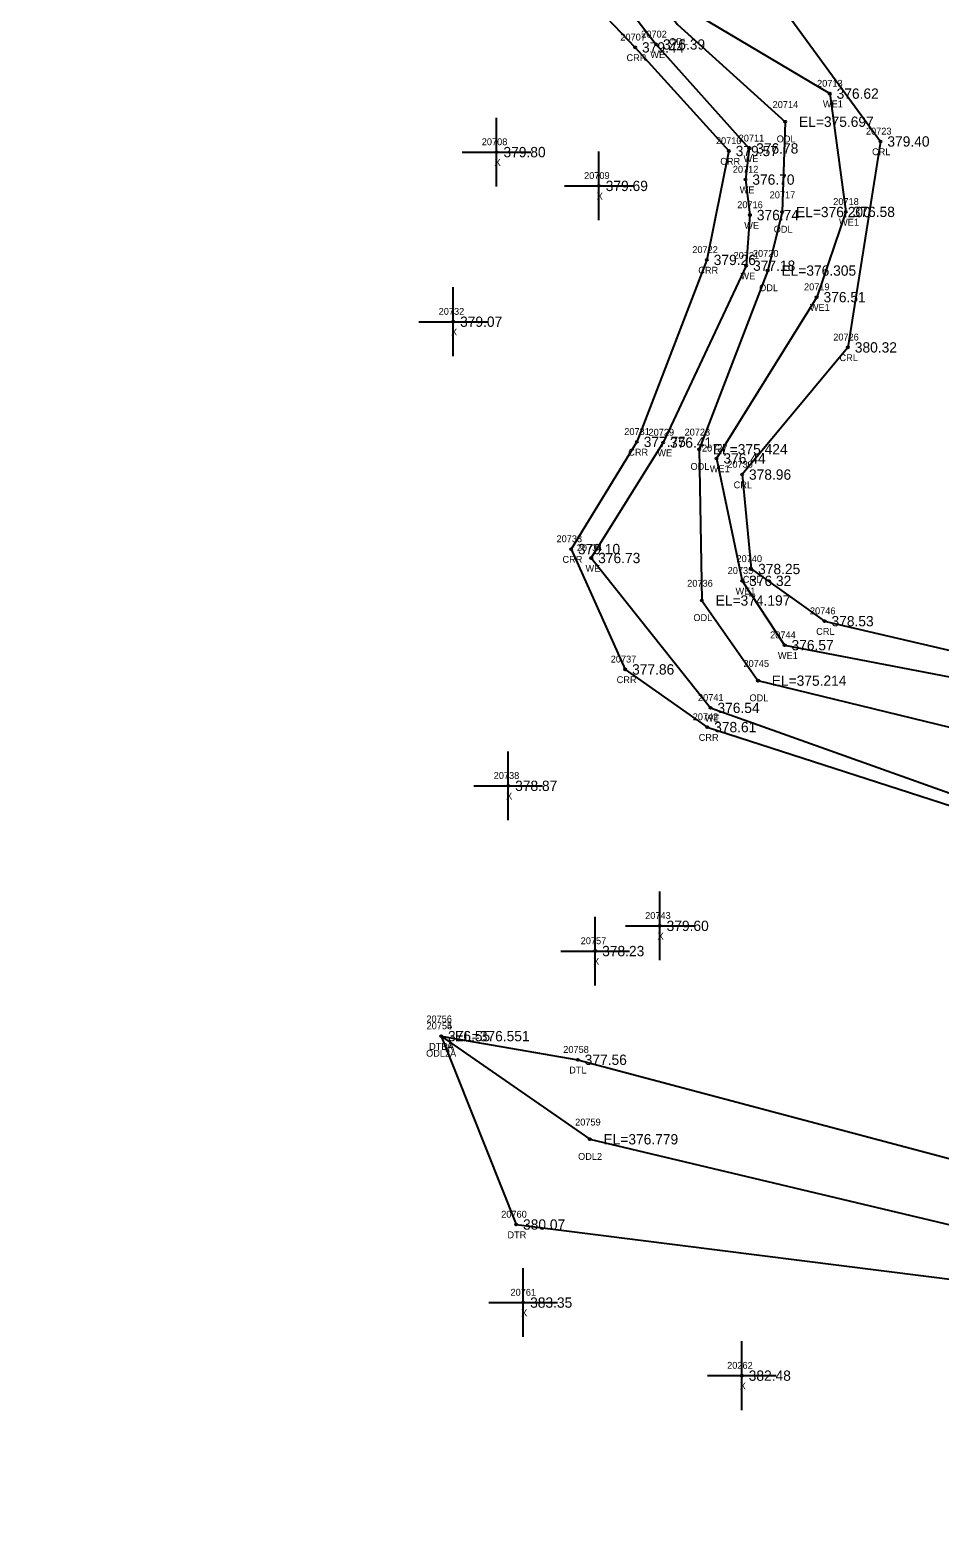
# Model space of a CAD drawing. Extents: x 2116373 to 2118139, y 979529 to 981026.
# Drawn here: x 2117048.4 to 2117180.8, y 980127.3 to 980346.7 of the extents above; entities that cross this region are included whole.
import ezdxf

# ---------------------------------------------------------------- set-up
doc = ezdxf.new("R2010")
doc.units = 0
for name, color, linetype in [('RD_EX_H2O', 7, 'Continuous'), ('RD_EX_H2O_txCode', 7, 'Continuous'), ('RD_EX_Misc', 7, 'Continuous'), ('RD_EX_Misc_txCode', 7, 'Continuous'), ('RD_EX_TX_H2O_ELEV', 7, 'Continuous'), ('RD_EX_TX_Misc_ELEV', 7, 'Continuous'), ('RD_SMD_Locator', 7, 'Continuous')]:
    doc.layers.add(name, color=color, linetype=linetype)

msp = doc.modelspace()

# ---------------------------------------------------------------- linework, layer by layer
at = {"layer": 'RD_EX_H2O'}
for points in [[(2117055.27, 980533.4), (2117084.87, 980468.5), (2117113.12, 980396.82), (2117150.26, 980360.48), (2117172.14, 980330.53), (2117167.4, 980300.56), (2117152, 980282.05), (2117153.33, 980268.31), (2117164.01, 980260.72), (2117221.6, 980247.26), (2117265.25, 980211.02), (2117324.27, 980199.15), (2117347.37, 980175.31), (2117365.85, 980182.55), (2117389.45, 980162.29), (2117399.63, 980142.01), (2117411.26, 980120.88), (2117420.42, 980068.64), (2117446.24, 980057.21), (2117497.11, 980045.39), (2117594.71, 979999.33), (2117646.33, 979985.56), (2117750.91, 980032.44), (2117805.09, 980018.87)], [(2117050.82, 980532.07), (2117080.88, 980466.55), (2117110.64, 980395.71), (2117144.25, 980349.68), (2117164.75, 980337.49), (2117167.1, 980320.28), (2117162.85, 980307.87), (2117148.28, 980284.4), (2117152.02, 980266.59), (2117158.19, 980257.22), (2117219.84, 980245.38), (2117260.42, 980200.03), (2117320.83, 980195.76), (2117348.44, 980166.4)], [(2117046.35, 980528.47), (2117072.74, 980464.26), (2117103.18, 980398.05), (2117142.6, 980347.56), (2117158.28, 980333.4), (2117157.84, 980320.26), (2117155.72, 980311.74), (2117145.74, 980285.73), (2117146.15, 980263.73), (2117154.31, 980252.06), (2117214.06, 980237.52), (2117257.08, 980196.51), (2117314.34, 980190.71), (2117327.56, 980176.76), (2117343.89, 980156.23)], [(2117042.29, 980526.09), (2117065.56, 980461.15), (2117099.14, 980397), (2117139.48, 980344.65), (2117153.05, 980329.52), (2117152.49, 980324.98), (2117153.14, 980319.82), (2117152.6, 980312.45), (2117140.5, 980286.71), (2117130.05, 980269.91), (2117147.41, 980248.1), (2117202.36, 980228.49), (2117250.8, 980193.52), (2117312.93, 980184.75), (2117333.66, 980167.27), (2117332.31, 980165.61), (2117330.39, 980165.66), (2117305.03, 980166.54), (2117306.15, 980158.45), (2117334.27, 980149.08), (2117359.88, 980134.92)], [(2117031.59, 980522.05), (2117061.22, 980460.91), (2117085.86, 980397.22), (2117136.43, 980344.22), (2117150.07, 980329.14), (2117146.87, 980313.29), (2117136.68, 980286.81), (2117127.11, 980271.21), (2117134.99, 980253.7), (2117146.93, 980245.3), (2117201.17, 980227.79), (2117241.16, 980199.52)], [(2117108.2, 980200.33), (2117129.82, 980185.32), (2117196.35, 980169.53), (2117205.12, 980176.93), (2117214.41, 980186.14), (2117250.8, 980193.52)], [(2117108.2, 980200.33), (2117119.12, 980172.91), (2117196.12, 980163.21), (2117213.19, 980174.82), (2117253.76, 980181.57)], [(2117108.2, 980200.33), (2117128.09, 980196.89), (2117197.27, 980178.49), (2117200.29, 980179.87), (2117210.97, 980190.02), (2117241.16, 980199.52)]]:
    msp.add_lwpolyline(points, dxfattribs=at)
at = {"layer": 'RD_EX_Misc'}
for p, q in [((2117116.27, 980323.98), (2117116.27, 980333.98)), ((2117111.27, 980328.98), (2117121.27, 980328.98)), ((2117131.15, 980319.06), (2117131.15, 980329.06)), ((2117126.15, 980324.06), (2117136.15, 980324.06)), ((2117109.96, 980299.3), (2117109.96, 980309.3)), ((2117104.96, 980304.3), (2117114.96, 980304.3)), ((2117117.97, 980231.76), (2117117.97, 980241.76)), ((2117112.97, 980236.76), (2117122.97, 980236.76)), ((2117140.01, 980211.38), (2117140.01, 980221.38)), ((2117130.63, 980207.71), (2117130.63, 980217.71)), ((2117135.01, 980216.38), (2117145.01, 980216.38)), ((2117125.63, 980212.71), (2117135.63, 980212.71)), ((2117120.15, 980156.55), (2117120.15, 980166.55)), ((2117115.15, 980161.55), (2117125.15, 980161.55)), ((2117151.96, 980145.92), (2117151.96, 980155.92)), ((2117146.96, 980150.92), (2117156.96, 980150.92))]:
    msp.add_line(p, q, dxfattribs=at)
at = {"layer": 'RD_SMD_Locator'}
for centre in [(2117136.43, 980344.22), (2117139.48, 980344.65), (2117164.75, 980337.49), (2117158.28, 980333.4), (2117172.14, 980330.53), (2117116.27, 980328.98), (2117150.07, 980329.14), (2117153.05, 980329.52), (2117131.15, 980324.06), (2117152.49, 980324.98), (2117153.14, 980319.82), (2117157.84, 980320.26), (2117167.1, 980320.28), (2117146.87, 980313.29), (2117152.6, 980312.45), (2117155.72, 980311.74), (2117162.85, 980307.87), (2117109.96, 980304.3), (2117167.4, 980300.56), (2117136.68, 980286.81), (2117140.5, 980286.71), (2117145.74, 980285.73), (2117148.28, 980284.4), (2117152, 980282.05), (2117127.11, 980271.21), (2117130.05, 980269.91), (2117153.33, 980268.31), (2117152.02, 980266.59), (2117146.15, 980263.73), (2117164.01, 980260.72), (2117158.19, 980257.22), (2117134.99, 980253.7), (2117154.31, 980252.06), (2117147.41, 980248.1), (2117146.93, 980245.3), (2117117.97, 980236.76), (2117140.01, 980216.38), (2117130.63, 980212.71), (2117108.2, 980200.33), (2117108.2, 980200.33), (2117108.2, 980200.33), (2117128.09, 980196.89), (2117129.82, 980185.32), (2117119.12, 980172.91), (2117120.15, 980161.55), (2117151.96, 980150.92)]:
    msp.add_circle(centre, 0.15, dxfattribs=at)

# ---------------------------------------------------------------- texts
at = {"layer": 'RD_EX_H2O_txCode'}
for s, p in [('20707', (2117134.28, 980345.22)), ('20702', (2117137.32, 980345.65)), ('WE', (2117138.64, 980342.65)), ('ODL', (2117141.36, 980344.56)), ('CRR', (2117135.18, 980342.22)), ('20713', (2117162.91, 980338.49)), ('20714', (2117156.44, 980335.4)), ('WE1', (2117163.76, 980335.49)), ('20710', (2117148.19, 980330.14)), ('20711', (2117151.5, 980330.52)), ('ODL', (2117157.03, 980330.4)), ('20723', (2117170.02, 980331.53)), ('WE', (2117152.21, 980327.52)), ('CRL', (2117170.91, 980328.53)), ('CRR', (2117148.82, 980327.14)), ('20712', (2117150.65, 980325.98)), ('WE', (2117151.65, 980322.98)), ('20716', (2117151.29, 980320.82)), ('20717', (2117156.01, 980322.26)), ('20718', (2117165.26, 980321.28)), ('WE', (2117152.31, 980317.82)), ('ODL', (2117156.6, 980317.26)), ('WE1', (2117166.11, 980318.28)), ('20722', (2117144.75, 980314.29)), ('20721', (2117150.76, 980313.45)), ('20720', (2117153.57, 980313.74)), ('CRR', (2117145.62, 980311.29)), ('WE', (2117151.76, 980310.45)), ('ODL', (2117154.48, 980308.74)), ('20719', (2117161.01, 980308.87)), ('WE1', (2117161.86, 980305.87)), ('20726', (2117165.26, 980301.56)), ('CRL', (2117166.17, 980298.56)), ('20731', (2117134.85, 980287.81)), ('20729', (2117138.38, 980287.71)), ('20728', (2117143.62, 980287.73)), ('CRR', (2117135.43, 980284.81)), ('WE', (2117139.66, 980284.71)), ('20727', (2117146.16, 980285.4)), ('ODL', (2117144.49, 980282.73)), ('WE1', (2117147.29, 980282.4)), ('20730', (2117149.84, 980283.05)), ('CRL', (2117150.77, 980280.05)), ('20733', (2117124.99, 980272.21)), ('20734', (2117127.93, 980270.91)), ('CRR', (2117125.86, 980269.21)), ('20740', (2117151.18, 980269.31)), ('WE', (2117129.21, 980267.91)), ('20735', (2117149.9, 980267.59)), ('CRL', (2117152.11, 980266.31)), ('20736', (2117144.01, 980265.73)), ('WE1', (2117151.04, 980264.59)), ('20746', (2117161.87, 980261.72)), ('ODL', (2117144.91, 980260.73)), ('20744', (2117156.08, 980258.22)), ('CRL', (2117162.78, 980258.72)), ('WE1', (2117157.21, 980255.22)), ('20737', (2117132.88, 980254.7)), ('20745', (2117152.2, 980254.06)), ('CRR', (2117133.74, 980251.7)), ('20741', (2117145.58, 980249.1)), ('ODL', (2117153.07, 980249.06)), ('20742', (2117144.81, 980246.3)), ('WE', (2117146.57, 980246.1)), ('CRR', (2117145.68, 980243.3)), ('20756', (2117106.05, 980202.33)), ('20754', (2117106.08, 980201.33)), ('20755', (2117106.08, 980201.33)), ('DTRA', (2117106.44, 980198.33)), ('DTLA', (2117106.46, 980198.33)), ('20758', (2117125.97, 980197.89)), ('ODL2A', (2117106.01, 980197.33)), ('DTL', (2117126.84, 980194.89)), ('20759', (2117127.7, 980187.32)), ('ODL2', (2117128.13, 980182.32)), ('20760', (2117116.94, 980173.91)), ('DTR', (2117117.85, 980170.91))]:
    msp.add_text(s, height=1, dxfattribs=at).set_placement(p)
at = {"layer": 'RD_EX_Misc_txCode'}
for s, p in [('20708', (2117114.11, 980329.98)), ('X', (2117115.96, 980326.98)), ('20709', (2117129, 980325.06)), ('X', (2117130.84, 980322.06)), ('20732', (2117107.84, 980305.3)), ('X', (2117109.64, 980302.3)), ('20738', (2117115.85, 980237.76)), ('X', (2117117.65, 980234.76)), ('20743', (2117137.89, 980217.38)), ('20757', (2117128.51, 980213.71)), ('X', (2117139.69, 980214.38)), ('X', (2117130.32, 980210.71)), ('20761', (2117118.29, 980162.55)), ('X', (2117119.84, 980159.55)), ('20262', (2117149.82, 980151.92)), ('X', (2117151.65, 980148.92))]:
    msp.add_text(s, height=1, dxfattribs=at).set_placement(p)
at = {"layer": 'RD_EX_TX_H2O_ELEV'}
for s, p in [('379.44', (2117137.43, 980343.47)), ('376.39', (2117140.48, 980343.9)), ('376.62', (2117165.75, 980336.74)), ('EL=375.697', (2117160.28, 980332.65)), ('379.40', (2117173.14, 980329.78)), ('379.57', (2117151.07, 980328.39)), ('376.78', (2117154.05, 980328.77)), ('376.70', (2117153.49, 980324.23)), ('376.74', (2117154.14, 980319.07)), ('EL=376.200', (2117159.84, 980319.51)), ('376.58', (2117168.1, 980319.53)), ('379.26', (2117147.87, 980312.54)), ('377.18', (2117153.6, 980311.7)), ('EL=376.305', (2117157.72, 980310.99)), ('376.51', (2117163.85, 980307.12)), ('380.32', (2117168.4, 980299.81)), ('377.75', (2117137.68, 980286.06)), ('376.41', (2117141.5, 980285.96)), ('EL=375.424', (2117147.74, 980284.98)), ('376.44', (2117149.28, 980283.65)), ('378.96', (2117153, 980281.3)), ('379.10', (2117128.11, 980270.46)), ('376.73', (2117131.05, 980269.16)), ('378.25', (2117154.33, 980267.56)), ('376.32', (2117153.02, 980265.84)), ('EL=374.197', (2117148.15, 980262.98)), ('378.53', (2117165.01, 980259.97)), ('376.57', (2117159.19, 980256.47)), ('377.86', (2117135.99, 980252.95)), ('EL=375.214', (2117156.31, 980251.31)), ('376.54', (2117148.41, 980247.35)), ('378.61', (2117147.93, 980244.55)), ('376.55', (2117109.2, 980199.58)), ('376.55', (2117109.2, 980199.58)), ('EL=376.551', (2117110.2, 980199.58)), ('377.56', (2117129.09, 980196.14)), ('EL=376.779', (2117131.82, 980184.57)), ('380.07', (2117120.12, 980172.16))]:
    msp.add_text(s, height=1.5, dxfattribs=at).set_placement(p)
at = {"layer": 'RD_EX_TX_Misc_ELEV'}
for s, p in [('379.80', (2117117.27, 980328.23)), ('379.69', (2117132.15, 980323.31)), ('379.07', (2117110.96, 980303.55)), ('378.87', (2117118.97, 980236.01)), ('379.60', (2117141.01, 980215.63)), ('378.23', (2117131.63, 980211.96)), ('383.35', (2117121.15, 980160.8)), ('382.48', (2117152.96, 980150.17))]:
    msp.add_text(s, height=1.5, dxfattribs=at).set_placement(p)

doc.saveas('drawing.dxf')
